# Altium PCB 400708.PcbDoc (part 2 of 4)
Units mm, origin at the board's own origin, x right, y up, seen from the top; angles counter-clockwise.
Board outline 117 x 63.5 mm, 4 copper layers (Top Layer, Mid-Layer 1, Mid-Layer 2, Bottom Layer), stack 1.556 mm thick; 226 components, 168 nets, 912 pads, 2002 vias.
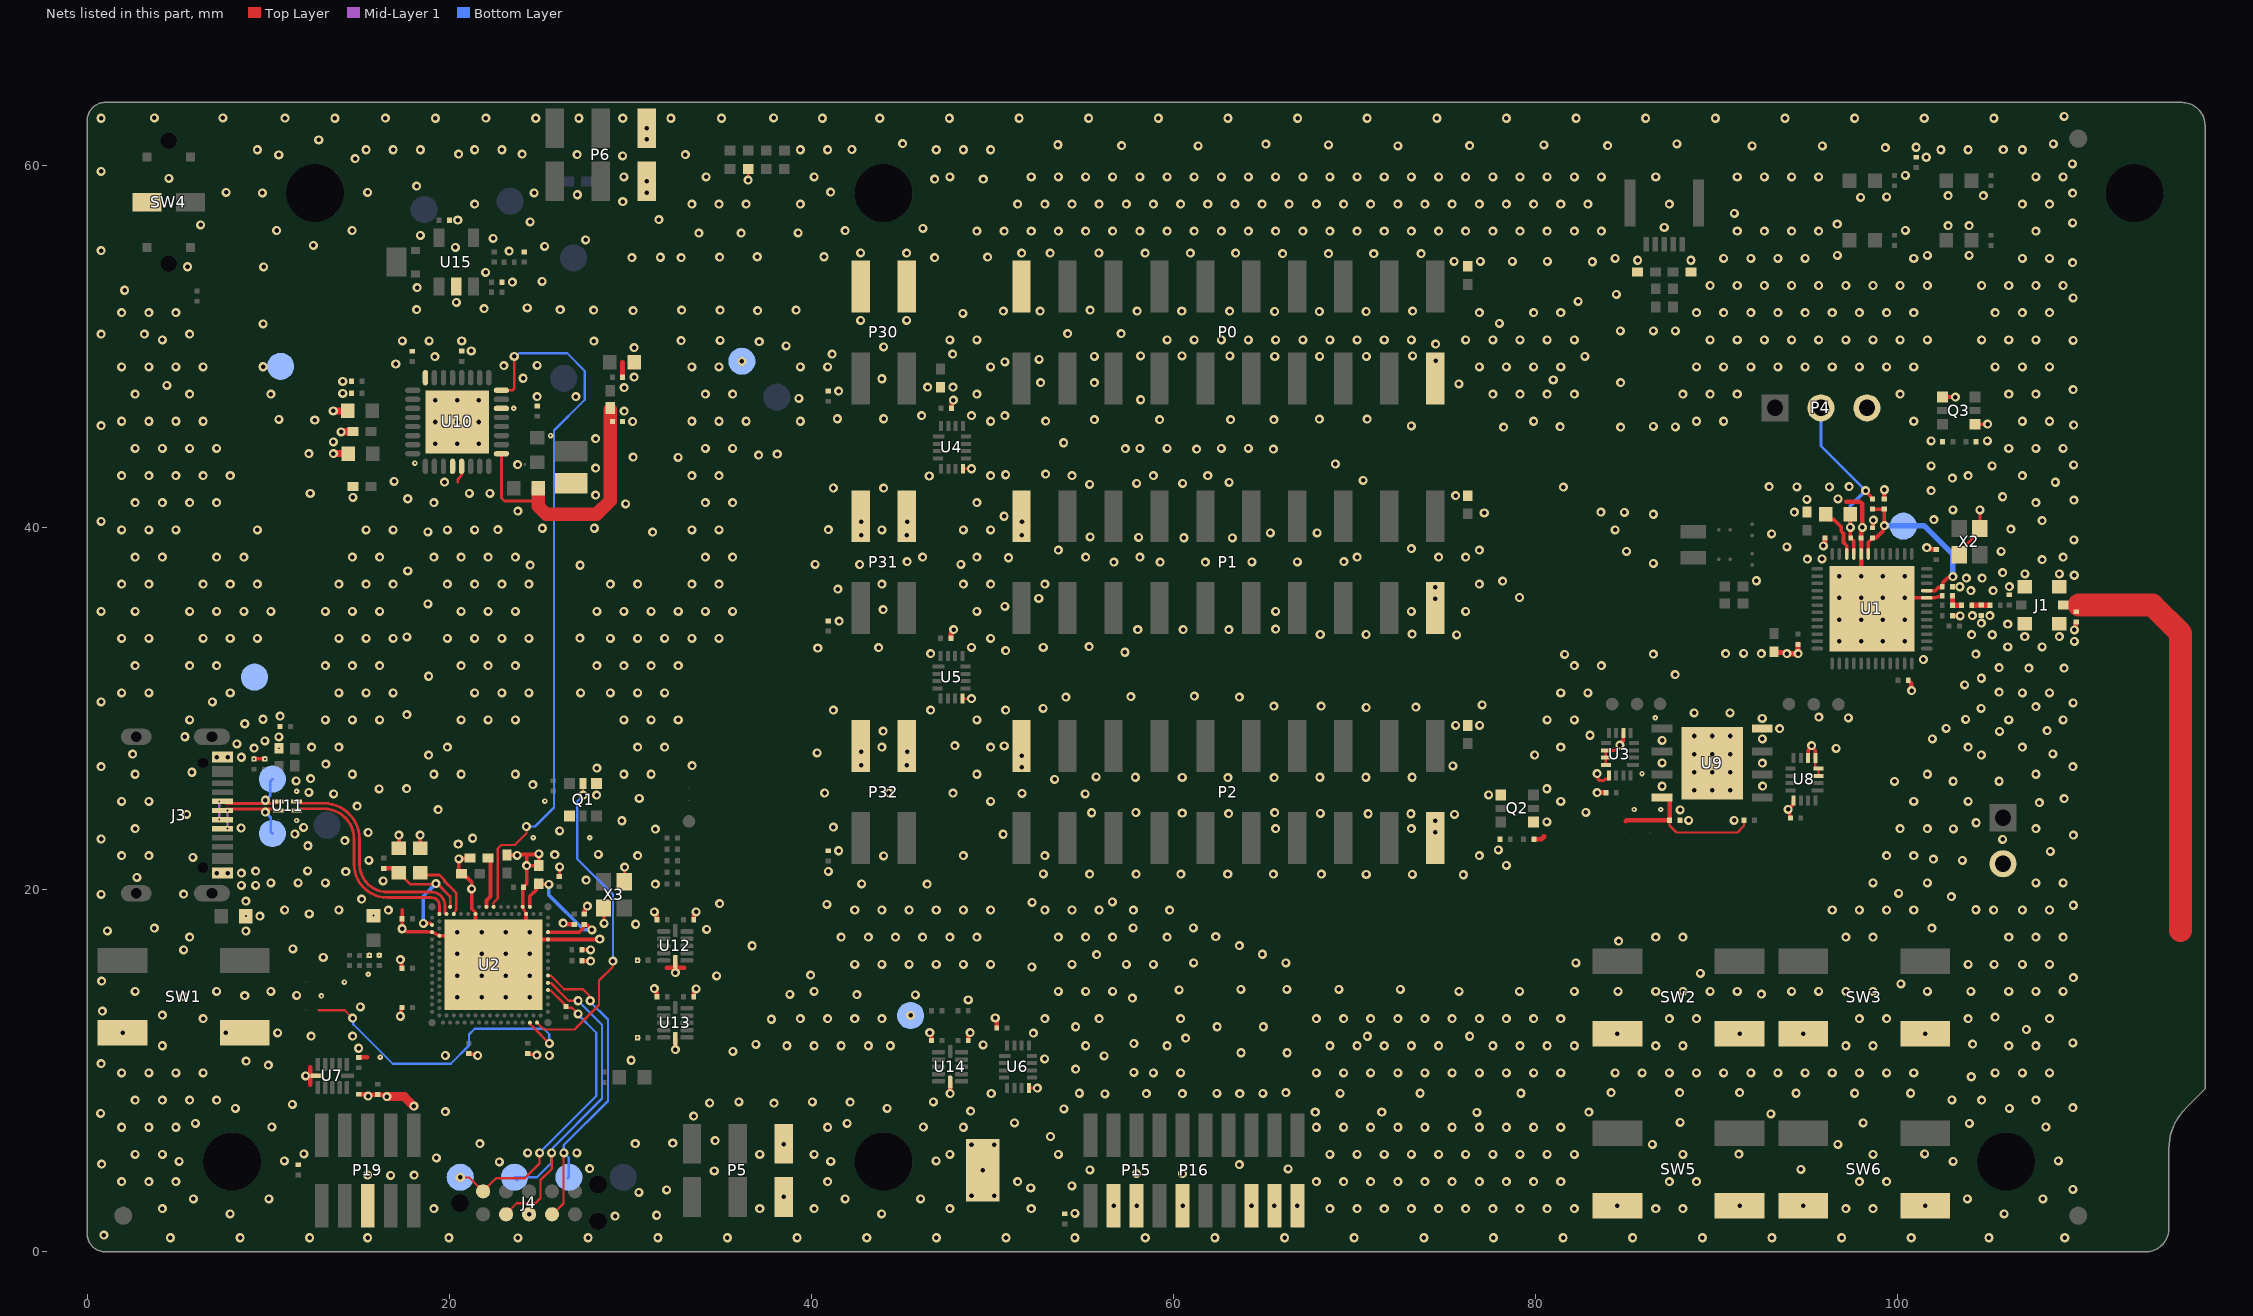
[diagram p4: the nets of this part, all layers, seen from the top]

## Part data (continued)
L3 L4: library part L0201-3n5-HQ-Murata, "Inductor, 500mA, ±0.1ｎH, 170mOhm", Manufacturer=Murata, Manufacturer Part Number=LQP03HQ3N5B02, Part number IPS=N.A., Part number NEMS=100300222, Supplier Part Number 1=490-13925-1-ND
L8: library part L0806-2µ2-2500mA-73mOhm-CIGT201610EH2R2MNE, "Inductor, Irms=2.5A, Isat=2.9A, ±20%, DCR=73mΩ", Manufacturer="Samsung Electro-Mechanics America", Manufacturer Part Number=CIGT201610EH2R2MNE, Part number IPS=N.A., Part number NEMS=100300400, Part number Norautron=26521789, Supplier Part Number 1=1276-6901-1-ND
LABEL1: library part Label_12x12, "PCA version label, stick-on, 12x12mm", Manufacturer="Ellco Etikett", Manufacturer Part Number=A33512‐01, Part number IPS=N.A., Part number NEMS=101200028
LD1 LD2 LD3 LD4 LD5: library part "VS 25C7M5", "LED, Green, 0603, 573nm, Vf=2.0V, 24mcd, - 40 to +85°C", Manufacturer="Victory Electronics", Part number IPS="00000001274, 00000009961", Part number NEMS=101400097, Part number Norautron=26313411, Supplier Part Number 1=N.A.
LOGO1: library part "Nordic Logo lying", "Nordic logo lying", Manufacturer=N.A., Part number NEMS=101100001
LOGO2: library part "WEEE Symbol 3x4.5mm", "WEEE Directive symbol", Manufacturer=N.A., Part number NEMS=101100006
LOGO3: "Segger logo, small size", Manufacturer=N.A., Part number NEMS=101100004
LOGO4: library part CE_logo, "CE (Conformité_Européenne) logo", Manufacturer=N.A., Part number NEMS=101100010
NT2: library part "2 pin starpoint", "Starpoint", Manufacturer=N.A., Part number NEMS=100500603
P0 P1 P2: library part "Pin Header 2x10 SMD, 2.54mm", "Pin Header 2x10, 2.54mm (100mil) SMD", Manufacturer=WCON, Manufacturer Part Number=1125-1210S0M116CR09, Part number IPS=N.A., Part number NEMS=100500738
P3: "Pin List 1x2, 2.54mm (100mil)", Manufacturer=N.A., Part number NEMS=100500297
P4: "Pin List 1x3, 2.54mm (100mil)", Manufacturer=N.A., Part number NEMS=100500304
P5 P6: library part "Pin List 1x3 SMD", "Pin List 1x3, 2.54mm (100mil), SMD", Manufacturer=WCON, Manufacturer Part Number=1125-1103S0M116CR04, Part number IPS=N.A., Part number NEMS=100500306, Part number Norautron=26470016
P15 P19: library part "Pin Header 2x5 SMD, 1.27mm, KS", "Pin Header 2x5, 1.27mm (50mil), SMD, Keying Shroud", Manufacturer=WCON, Manufacturer Part Number=3132-10MS0BK00R5, Part number IPS=N.A., Part number NEMS=100500261
P16: library part "Pin Header 2x10 SMD, 1.27mm, KS, N.C.", "Pin Header 2x10, 1.27mm (50mil), SMD, Keying Shroud", Manufacturer=WCON, Manufacturer Part Number=3132-20MS0BK00R1, Part number IPS=N.A., Part number NEMS=100500279
P30 P31 P32: "Pin Header 2x2, SMD, 2.54mm (100mil)", Manufacturer=WCON, Manufacturer Part Number=1125-1202S0M116CR03, Part number IPS=N.A., Part number NEMS=100500770
Q1 Q2 Q3: "MOSFET 2N-CH 60V 0.17A TSSOP6 (SOT363)", Manufacturer=Nexperia, Manufacturer Part Number=NX138AKSX, Part number IPS=N.A., Part number NEMS=101300207, Supplier Part Number 1=1727-2732-2-ND
Q4: library part PBSS4330PA,115, "30V, 3A, 2.1W, G=270, NPN Transistor", Manufacturer=Nexperia, Part number IPS=N.A., Part number NEMS=101300184, Supplier Part Number 1=1727-5112-1-ND‎
R1 R2 R19 R20: library part R0201-680, "Resistor, ±1%, 0.05W", Manufacturer=N.A., Part number NEMS=100100040
R3 R9 R38: library part R0201-0R, "Resistor, ±5%, 0.05W", Manufacturer=N.A., Part number IPS=00000003245, Part number NEMS=100100001
R4 R37 R41 R42: library part R0201-10k, "Resistor, ±1%, 0.05W", Manufacturer=N.A., Part number IPS=00000001255, Part number NEMS=100100065, Part number Norautron=26107101
R5: library part R0201-560, "Resistor, ±1%, 0.05W", Manufacturer=N.A., Part number NEMS=100100038
R6 R8 R13 R14 R15 R16 R17 R23 R31 R32 R35 R39 R56: library part R0201-100k, "Resistor, ±1%, 0.05W", Manufacturer=N.A., Part number IPS=00000001419, Part number NEMS=100100080, Part number Norautron=26108487
R7: library part R0201-47R, "Resistor, ±1%, 0.05W", Manufacturer=N.A., Part number IPS=00000004794, Part number NEMS=100100022, Part number Norautron=26108300
R10 R11 R12 R18 R27: library part R0201-1M0, "Resistor, ±1%, 0.05W", Manufacturer=N.A., Part number IPS=00000001418, Part number NEMS=100100093, Part number Norautron=26107108
R21 R22 R25 R28 R29 R30 R33 R34: library part R0402-0R, "Resistor, ±5%, 0.063W", Manufacturer=N.A., Part number IPS=00000007128, Part number NEMS=100100109, Supplier Part Number 1=146-9661
R24: library part R0402-TBD, "Chip Res 0402", Manufacturer=N.A., Part number NEMS=100100282
R26: library part R0201-47k, "Resistor, ±1%, 0.05W", Manufacturer=N.A., Part number IPS=00000001423, Part number NEMS=100100076
R36: library part R0201-1k0, "Resistor, ±1%, 0.05W", Manufacturer=N.A., Part number IPS=00000005786, Part number NEMS=100100043
R40: library part R0201-2R2, "Resistor, ±1%, 0.05W", Manufacturer=N.A., Part number NEMS=100100006, Part number Norautron=26470029
R43: library part R0201-33k, "Resistor, ±1%, 0.05W", Manufacturer=N.A., Part number IPS=00000001708, Part number NEMS=100100073
S1: "Giteki symbol", Manufacturer=N.A., Part number NEMS=101100011
SB1 SB8 SB10: Manufacturer=N.A., Part number NEMS=100500458
SB2 SB9 SB11: library part "Solderbridge Shorted", "Shorted Solderbridge", Manufacturer=N.A., Part number NEMS=100500459
SB3 SB4: library part "Solderbridge Shorted 0.4mm", "Shorted Solderbridge", Manufacturer=N.A., Part number NEMS=100500561
SB5 SB6: library part "Solderbridge 0.4mm", Manufacturer=N.A., Part number NEMS=100500560
SW1 SW2 SW3 SW5 SW6: library part Switch-PB-6.2x6.3mm-SMD, "Tactile Switch, SPNO, SMD, 160gf, 6.2x6.3x2.5mm", Manufacturer=Dailywell, Manufacturer Part Number=TS604VM1-025BR-R, Part number IPS=00000007812, Part number NEMS="101500001, 101500133", Part number Norautron=N.A.
SW4: library part Switch-Slide-RA-J-Lead-DPDT-8.5x3.5mm_C&K, "SMD slide Switch (ON-ON)", Manufacturer=C&K, Manufacturer Part Number=JS202011JAQN, Part number IPS=00000007811, Part number NEMS=101500037, Part number Norautron=N.A., Supplier Part Number 1=CKN10722CT-ND
TP1 TP2 TP3 TP4 TP5 TP6 TP8 TP9 TP10 TP11 TP12 TP13 TP14 TP15 TP16 TP17 TP18: library part TP_SMD_Ø1.5MM, "1.5mm circular SMD testpad", Manufacturer="Nordic Semiconductor", Manufacturer Part Number=N.A., Part number NEMS=100500477
TP7 TP19 TP20 TP21 TP23 TP24 TP25: library part TP_SMD_Ø0.7MM, "0.7mm circular SMD testpad", Manufacturer="Nordic Semiconductor", Manufacturer Part Number=N.A., Part number NEMS=100500474
TP22: library part "TP - S1751-46R", "PC TEST POINT TIN SMD L", Manufacturer=Harwin, Manufacturer Part Number=S1751-46R, Part number IPS=N.A., Part number NEMS=100500525, Supplier Part Number 1=952-1478-1-ND
U1: library part nRF54L15-QFAAC00, "Multi-protocol Bluetooth Low Energy, IEEE 802.15.4 and 2.4GHz proprietary Wireless MCU", Manufacturer="Nordic Semiconductor", Part number IPS=N.A., Part number NEMS=102000382
U2: library part nRF5340-QKAAD0, "Multi-protocol Bluetooth Low Energy, IEEE 802.15.4, ANT and 2.4GHz proprietary system-on-chip", Manufacturer="Nordic Semiconductor", Part number IPS=N.A., Part number NEMS=102000216, Part number Norautron=NOD26470035
U3 U8: "Low-Capacitance, 2:1 (SPDT) 4-Channel, analog switch", Manufacturer="Texas Instruments", Manufacturer Part Number=TMUX1574RSVR, Part number IPS=N.A., Part number NEMS=101900850, Supplier Part Number 1=296-53445-2-ND
U4 U5 U6: "Low-Capacitance, 1:1 (SPST) 4-Channel, analog switch", Manufacturer="Texas Instruments", Manufacturer Part Number=TMUX1511RSVR, Part number IPS=N.A., Part number NEMS=101900847, Supplier Part Number 1=296-53443-2-ND
U7 U12 U13 U14: library part TXB0104RUTR, "4-Bit Bidirectional Level-Shifter/Voltage Translator with Automatic Direction Sensing", Manufacturer="Texas Instruments", Part number IPS=N.A., Part number NEMS=101900856, Supplier Part Number 1=296-25888-2-ND
U9: library part MX25R6435FZNIL0, "Ultra low power, 64M-bit, serial multi I/O flash memory", Manufacturer=Macronix, Part number IPS=00000004370, Part number NEMS=101900438, Part number Norautron=N.A.
U10: "Li-Ion/Li-Polymer USB-C battery charger with high efficiency buck regulators, LDOs or load switches, LED drivers, TWI and VBUSOUT", Manufacturer="Nordic Semiconductor", Part number IPS=N.A., Part number NEMS=102000306
U11: "2 Line Common mode filter with ESD protection for USB 2.0 interface", Manufacturer=STMicroelectronics, Part number IPS=N.A., Part number NEMS=100800034, Supplier Part Number 1=497-13420-2-ND
U15: library part TLV271CW5-7, "Dual rail to rail CMOS Amplifier", Manufacturer="Diodes Incorporated", Part number IPS=N.A., Part number NEMS=101900398, Supplier Part Number 1=TLV271CW5-7DICT-ND
X1: library part XTAL_SMD2012_32.768kHz_9pF_TXC, "XTAL SMD 2012, 32.768kHz, 9pF, ±20ppm", Manufacturer="TXC Corporation", Manufacturer Part Number=9HT11-32.768KDZC-T, Part number IPS=N.A., Part number NEMS=101600107, Supplier Part Number 1=887-1426-2-ND
X2 X3: library part XTAL_SMD2016_32MHz_8pF_Golledge, "XTAL SMD 2016, 32MHz, Cl=8pF, Tol: ±10ppm, Stab: ±15ppm", Manufacturer=Golledge, Manufacturer Part Number=MP06003, Part number IPS=00000001431, Part number NEMS=101600041, Part number Norautron=N.A.

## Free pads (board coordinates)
  round 3.2 hole 3.2 unplated: 1(8.004,5) 1(12.604,58.5) 1(44.004,5) 1(44.004,58.5) 1(106.004,5) 1(113.104,58.5)

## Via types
v1: diameter 0.5, hole 0.25, Top Layer to Bottom Layer, tented both sides, 1905 vias
v2: diameter 0.3, hole 0.1, Top Layer to Mid-Layer 1, tented top, 77 vias
v3: diameter 0.3, hole 0.1, Top Layer to Mid-Layer 1, tented both sides, 20 vias

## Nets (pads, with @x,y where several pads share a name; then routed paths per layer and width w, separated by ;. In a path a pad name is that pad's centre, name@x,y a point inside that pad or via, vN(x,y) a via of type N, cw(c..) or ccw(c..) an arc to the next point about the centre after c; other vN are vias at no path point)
ANT: C38.2 J1.3 | length 22.7
  Top Layer w1.27: 110.033,35.73 114.1,35.73 115.66,34.171 115.66,17.748
DBGR'_N: J3.A7 J3.B7 TP17.1 U11.2 | length 5.5
  Top Layer w0.153: J3.B7@7.489,24.875 ccw(c7.727,25.113) 7.727,24.776 10.322,24.776 ccw(c10.322,25.141) U11.2@10.579,24.883
  Mid-Layer 1 w0.127: v2(7.3,23.884) v2(7.3,24.884)
  Bottom Layer w0.153: v1(9.85,24.95) 10.125,25.225 10.125,26 TP17.1@10.24,26.115
DBGR'_P: J3.A6 J3.B6 TP18.1 U11.3 | length 5.5
  Top Layer w0.153: J3.A6@7.489,24.375 cw(c7.727,24.137) 7.727,24.473 10.361,24.473 cw(c10.361,24.165) U11.3@10.579,24.383
  Mid-Layer 1 w0.127: v2(7.763,23.385) v2@7.763,24.374
  Bottom Layer w0.153: v1(9.85,24.3) 10.147,24.003 10.147,23.206 TP18.1@10.24,23.113
  other v2: 7.763,24.385
DBGR_BUTTON: SB2.2 U2.AL27 | length 17.6
  Top Layer w0.125: SB2.2@12.8,13.364 12.815,13.35 14.237,13.35 v1(14.675,12.912) ; U2.AL27@24.46,12.664 24.46,12.637 24.51,12.587 24.51,12.555 24.631,12.434 24.631,12.427 v1(25.54,11.518)
  Top Layer w0.15: U2.AL27@24.46,12.622 U2.AL27@24.46,12.637
  Bottom Layer w0.125: v1(14.675,12.912) 14.703,12.884 14.703,12.572 16.888,10.387 20.087,10.387 21.1,11.4 21.1,12.009 21.416,12.325 25.244,12.325 25.54,12.03 v1(25.54,11.518)
DBGR_LED: Q1.2 U2.AL29 | length 17.5
  Top Layer w0.125: U2.AL29@24.86,12.664 25.237,12.288 26.938,12.288 27.124,12.474 28.286,13.636 28.286,14.986 29.023,15.723 29.023,16.037 v1(29.05,16.064) ; v1(27.401,25.234) Q1.2@27.401,25.71
  Bottom Layer w0.125: v1(27.401,25.234) 27.401,25.199 27.079,24.878 27.079,21.71 29.05,19.739 v1(29.05,16.064)
DBGR_N: U2.B4 U11.7 | length 12.6
  Top Layer w0.153: U11.7@11.579,24.883 ccw(c11.833,25.137) 11.833,24.778 13.084,24.778 cw(c13.084,22.81) 15.053,22.81 15.053,21.422 ccw(c16.6,21.422) 16.6,19.875 19.033,19.875 cw(c19.033,19.138) 19.77,19.138 19.77,18.755 ccw(c19.86,18.755) U2.B4@19.86,18.664
DBGR_P: U2.B2 U11.6 | length 12
  Top Layer w0.153: U11.6@11.579,24.383 cw(c11.801,24.161) 11.801,24.475 13.084,24.475 cw(c13.084,22.81) 14.75,22.81 14.75,21.422 ccw(c16.6,21.422) 16.6,19.572 19.033,19.572 cw(c19.033,19.138) 19.467,19.138 19.467,18.664 U2.B2@19.46,18.664
DBGR_RESET: J4.10 R6.1 TP4.1 U2.AC31 | length 17.6
  Top Layer w0.125: v1(20.616,4.115) 21.107,4.115 J4.10@21.878,3.344 22.609,4.075 24.2,4.075 25.001,4.876 v1(25.001,5.475) ; U2.AC31@25.46,14.464 25.479,14.445 25.616,14.445 26.372,13.689 26.372,13.628 26.517,13.483 26.792,13.483 v1(27.125,13.15)
  Bottom Layer w0.125: v1(25.001,5.475) 28.132,8.606 28.132,12.107 27.125,13.114 v1(27.125,13.15)
DBGR_SWDCLK: J4.4 TP6.1 U2.W31 | length 18
  Top Layer w0.125: U2.W31@25.46,15.264 25.471,15.254 25.624,15.254 26.363,14.515 27.124,14.515 27.393,14.515 27.732,14.176 27.732,13.943 v1(27.8,13.875) ; J4.4@25.688,2.074 25.724,2.074 26.324,2.674 26.324,5.459 v1(26.34,5.475)
  Bottom Layer w0.125: TP6.1@26.558,4.067 TP6.1@26.564,4.062 ; TP6.1@26.616,4.125 26.616,5.198 v1(26.34,5.475) 26.34,5.903 28.775,8.339 28.775,12.832 27.8,13.808 v1(27.8,13.875)
DBGR_SWDIO: J4.2 TP5.1 U2.AA31 | length 20.4
  Top Layer w0.125: J4.2@23.148,2.074 23.148,2.099 23.74,2.69 24.771,2.69 25.053,2.972 25.053,3.968 25.667,4.582 v1(25.667,5.475) ; U2.AA31@25.46,14.864 25.471,14.854 25.624,14.854 26.603,13.875 v1(27.125,13.875)
  Bottom Layer w0.125: TP5.1@23.616,4.125 24.851,4.125 25.667,4.94 v1(25.667,5.475) 25.738,5.547 25.738,5.76 28.452,8.473 28.452,12.548 v1(27.125,13.875)
  Bottom Layer w0.15: TP5.1@23.616,4.115 TP5.1@23.759,3.972
DCC: L1.2 U1.46 | length 2.8
  Top Layer w0.2: L1.2@96.053,40.758 96.053,40.733 96.328,40.458 96.496,40.458 96.906,40.048 96.906,39.818 97.033,39.691 97.033,39.186 97.205,39.014 U1.46@97.205,38.555
DECD: C1.2 FB1.1 L1.1 P4.2 U1.45 | length 10.9
  Top Layer w0.2: L1.1@97.414,40.798 v1(97.414,40.022) 97.414,39.46 C1.2@97.435,39.439 97.435,39.424 97.47,39.389 97.485,39.389 97.605,39.269 97.605,38.78 U1.45@97.605,38.555 ; v1(98.25,42.05) 98.25,42.024 98.583,41.691 98.583,41.637 FB1.1@98.637,41.637
  Bottom Layer w0.15: P4.2@95.785,46.625 95.785,44.515 v1(98.25,42.05)
  Bottom Layer w0.2: v1(97.414,40.022) 97.414,41.214 v1(98.25,42.05)
DECRF: C2.2 C5.2 C12.1 FB1.2 TP2.1 U1.33 U1.43 | length 11.2
  Top Layer w0.2: U1.43@98.405,38.555 98.405,39.204 98.668,39.467 98.856,39.467 99.236,39.847 99.236,40.066 v1(99.294,40.123) C2.2@99.294,41.032 FB1.2@98.633,41.032 ; U1.33@101.63,36.53 102.093,36.53 102.263,36.7 102.453,36.7 102.488,36.735 102.488,36.745 102.523,36.78 102.523,36.975 102.795,37.246 103.021,37.246 v1(103.078,37.304)
  Bottom Layer w0.15: TP2.1@100.252,40.123 TP2.1@100.273,40.144
  Bottom Layer w0.3: v1(99.294,40.123) 100.252,40.123 101.478,40.123 103.078,38.523 v1(103.078,37.304)
GND: C1.1 C2.1 C3.1 C4.2 C5.1 C6.1 C7.2 C8.2 C9.1 C10.2 C11.2 C12.2 C13.2 C14.2 C15.2 C16.1 C17.2 C18.2 C19.1 C20.2 C21.2 C22.2 C23.1 C25.1 C26.1 C28.1 C29.2 C30.2 C31.2 C32.1 C33.2 C34.2 C35.2 C36.2 C37.2 C38.1 C39.1 C40.2 C41.1 C42.2 C43.2 C44.2 C45.1 C46.1 C47.1 C48.1 C49.2 C50.1 C51.1 C52.1 C53.1 C54.2 C55.1 C56.1 C57.1 C58.2 C59.2 C60.2 C61.1 C62.1 C63.1 C64.1 C65.2 C66.2 C67.2 C68.1 C69.2 C70.1 C72.2 C73.1 C74.2 C75.2 C76.2 C77.2 C78.2 C79.2 J1.2 J3.A1 J3.A12 J4.3 NT2.1 P0.2 P0.19 P1.2 P1.19 P2.2 P2.19 P3.2 P4.3 P5.1 P6.1 P15.3 P15.5 P15.9 P16.3 P16.5 P16.9 P16.15 P16.17 P16.19 P19.5 P30.2 P30.4 P31.2 P31.4 P32.2 P32.4 Q1.1 Q1.4 Q2.1 Q2.4 Q3.1 Q3.4 R4.1 R7.2 R10.2 R11.2 R12.2 R18.1 R26.2 R27.2 R30.2 R32.2 R37.1 R42.1 R56.2 SW1.1 SW2.1 SW3.1 SW4.2 SW5.1 SW6.1 TP12.1 TP13.1 TP14.1 TP15.1 TP22.1 U1.32 U1.44 U1.49 U2.104 U2.A25 U2.B12 U2.B26 U2.G1 U2.H2 U2.J31 U3.6 U3.10 U3.11 U3.12 U3.13 U4.8 U5.8 U6.8 U7.6 U8.3 U8.4 U8.5 U8.6 U8.13 U9.4 U9.9 U10.6 U10.16 U10.28 U10.29 U10.33 U11.5 U11.8 U12.6 U13.6 U14.6 U15.2 X2.2 X2.4 X3.2 X3.4 | length 75.6
  Top Layer w0.125: C65.2@83.9,25.385 C65.2@83.905,25.39 ; U3.10@83.9,27.7 U3.11@83.9,27.3 U3.12@83.9,26.9 84.028,26.9 U3.12@84.075,26.853 ; U8.5@95.475,27.275 95.475,26.747 95.522,26.7 U8.4@95.65,26.7 U8.3@95.65,26.3
  Top Layer w0.15: U10.16@18.678,48.31 U10.16@18.692,48.296 ; 20.478,42.525 20.478,42.678 20.691,42.891 U10.29@20.692,43.396 ; C37.2@26.096,20.744 26.103,20.751 26.103,21.258 v1(26.11,21.265) ; X3.4@28.534,18.99 28.56,18.965 v1(28.56,18.147) ; X3.2@29.677,20.448 29.7,20.471 v1(29.7,21.258) ; v1(36.525,59.207) R30.2@36.525,59.83 ; U5.8@48.36,30.561 v1(48.86,30.561) ; U4.8@48.378,43.262 v1(48.86,43.262) ; U6.8@52.025,9.05 v1(52.496,9.05) ; v1(83.425,26.425) 83.472,26.378 83.472,26.1 83.53,26.042 83.792,26.042 83.875,26.125 84.04,26.125 84.075,26.16 U3.13@84.075,26.325 ; U3.10@83.9,27.7 84.375,27.7 v1(84.675,28) ; X2.4@103.418,38.509 103.768,38.859 103.768,39.026 104.218,39.476 104.218,39.609 X2.2@104.568,39.959 ; X2.2@104.568,39.934 X2.2@104.568,39.959 ; v1(104.568,40.987) X2.2@104.568,39.959
  Top Layer w0.165: U2.A25@24.06,19.064 U2.B26@24.26,18.664
  Top Layer w0.187: U2.G1@19.06,17.664 U2.H2@19.46,17.464 U2.104@20.16,17.464 ; v1(21.245,20.052) 21.245,18.96 21.453,18.752 21.453,18.672 U2.B12@21.46,18.664
  Top Layer w0.188: 18.183,17.694 18.832,17.694 18.856,17.669 19.055,17.669 U2.G1@19.06,17.664
  Top Layer w0.2: v3(9.225,27.235) v3(9.825,27.235) ; C42.2@17.231,22.302 v1(17.231,23.024) ; v1(17.308,13.017) 17.365,13.074 17.365,13.436 C20.2@17.428,13.499 ; v1(17.313,16.149) 17.369,16.094 17.369,15.659 C18.2@17.404,15.624 ; 17.404,18.9 17.404,18.864 C13.2@17.404,18.401 v1(17.404,17.853) 17.485,17.853 17.644,17.694 18.183,17.694 ; C43.2@18.4,22.302 v1(18.4,23.025) ; v1@20.529,21.735 20.529,21.041 20.679,20.891 C45.1@20.694,20.891 ; v1(20.538,21.706) 20.562,21.73 21.236,21.73 C39.1@21.262,21.756 ; C45.1@20.719,20.916 20.894,20.741 20.932,20.741 21.243,20.429 21.243,20.054 v1(21.245,20.052) ; C22.2@21.092,10.954 21.127,10.919 21.431,10.919 21.5,10.85 v1(21.581,10.85) ; U2.A25@24.06,19.064 24.06,19.987 24.085,20.012 24.085,20.134 24.285,20.334 v1(24.285,21.34) ; 24.262,21.951 24.285,21.929 v1(24.285,21.34) ; C34.2@24.343,10.954 24.378,10.919 24.806,10.919 v1(24.85,10.875) ; v1(24.96,21.988) 24.957,21.984 24.957,21.343 C32.1@24.953,21.34 v1(24.285,21.34) ; Q1.1@27.964,25.91 28.158,25.716 Q1.1@28.164,25.716 ; v1(84.675,28) 84.675,28.05 84.875,28.25 U3.6@84.875,28.675 ; C66.2@94.1,23.971 94.065,24.006 94.065,24.273 93.978,24.359 v1(93.978,24.44) 94.265,24.727 94.265,24.915 U8.13@94.275,24.925 ; U8.6@95.075,27.275 95.075,27.715 v1@95.275,27.915 ; v1(95.275,27.965) v1@95.275,27.915 ; U8.5@95.475,27.275 95.475,27.715 v1@95.275,27.915 ; C12.2@98.633,40.002 98.659,40.027 98.659,40.403 v1(98.684,40.428) ; U1.49@100.443,36.13 U1.32@101.63,36.13 102.06,36.13 C6.1@102.487,36.244 ; Q3.1@102.5,47.225 v1(103.216,47.225) ; Q3.4@104.3,45.725 v1@105.016,45.725
  Top Layer w0.203: R7.2@27.345,16.687 v1(27.823,16.687) ; C35.2@27.353,16.078 27.36,16.071 27.816,16.071 v1(27.823,16.064)
  Top Layer w0.225: U2.104@21.46,17.264 U2.B12@21.46,18.664 ; C31.2@23.15,21.905 C31.2@23.16,21.915 ; C31.2@23.211,21.915 23.751,21.915 v1(23.759,21.907) 23.804,21.951 24.262,21.951 24.924,21.951 v1(24.96,21.988) ; U2.B26@24.26,18.664 24.26,17.264 28.314,17.264 v1(28.325,17.275) ; C33.2@27.459,18.661 27.474,18.661 27.496,18.683 27.496,18.879 27.644,19.027 v1(27.644,19.101)
  Top Layer w0.25: v1(12.075,9.725) U7.6@12.7,9.725 ; 12.34,9.244 12.34,10.2 ; C14.2@15.004,8.707 15.014,8.697 15.36,8.697 15.457,8.6 v1(15.525,8.6) 15.593,8.6 15.675,8.682 16.054,8.682 R18.1@16.064,8.692 16.074,8.682 16.391,8.682 16.493,8.58 v1(16.56,8.58) ; C53.1@15.004,10.744 15.468,10.744 ; v1(26.299,18.167) 26.367,18.167 26.433,18.101 26.899,18.101 C36.2@26.909,18.091 ; v1(31.346,14.539) 31.346,14.471 31.471,14.346 31.471,14.114 C76.2@31.481,14.104 ; v1(31.346,18.789) 31.346,18.721 31.471,18.596 31.471,18.364 C74.2@31.481,18.354 ; 32.025,15.69 32.981,15.69 ; v1(32.5,11.175) U13.6@32.5,11.8 ; v1(32.5,15.425) U12.6@32.5,16.05 ; C77.2@33.518,14.094 33.528,14.104 33.528,14.341 33.653,14.466 v1(33.653,14.533) ; C75.2@33.518,18.354 33.528,18.364 33.528,18.596 33.653,18.721 v1(33.653,18.789) ; v1(46.555,12.114) 46.555,12.046 46.644,11.957 46.644,11.689 C78.2@46.654,11.679 ; v1(47.675,8.75) U14.6@47.675,9.375 ; C15.2@47.718,33.903 47.728,33.913 47.728,34.168 47.868,34.307 v1(47.868,34.375) ; C10.2@47.752,46.607 47.762,46.617 47.762,46.894 47.856,46.989 v1(47.856,47.056) ; C79.2@48.68,11.679 48.69,11.689 48.69,11.956 48.78,12.046 v1(48.78,12.114) ; v1(50.172,12.931) 50.172,12.864 50.245,12.79 50.245,12.379 C49.2@50.255,12.369 ; v1@95.915,39.068 v1@95.915,39.073 ; 97.195,41.453 97.938,41.453 98.074,41.317 v1(98.074,40.022) 98.074,39.954 98.015,39.895 98.015,39.449 C1.1@98.005,39.439 U1.44@98.005,38.555 v1(98.005,37.33) ; C2.1@99.294,41.602 v1(99.294,42.104) ; C8.2@100.61,31.575 100.61,31.56 100.62,31.55 100.624,31.55 100.77,31.404 100.77,31.027 v1(100.792,31.005) ; v1(101.63,38.904) 101.698,38.904 101.784,38.818 102.154,38.818 C4.2@102.164,38.808 ; C60.2@103.058,35.149 103.063,35.144 103.466,35.144 v1(103.471,35.139) ; v1(109.789,34.36) 109.789,34.427 109.855,34.493 109.855,34.785 109.865,34.795 C38.1@109.88,34.795
  Top Layer w0.254: X3.4@28.531,18.994 X3.4@28.534,18.99 ; X3.2@29.677,20.448 X3.2@29.681,20.444
  Top Layer w0.27: C25.1@29.59,48.321 29.59,49.147 ; R10.2@79.925,22.798 80.344,22.798 80.488,22.942 ; v1(83.425,25.375) 83.429,25.371 83.908,25.371 C65.2@83.908,25.365 ; C19.1@85.652,54.123 C19.1@85.654,54.124 ; v1@85.654,54.779 v1(85.656,54.781) ; v1(95.915,39.006) 95.915,39.068 96,39.153 C11.2@96,39.439
  Top Layer w0.3: C41.1@93.186,33.155 93.23,33.112 93.798,33.112 93.855,33.055 v1(93.909,33.055) v1(94.53,33.055) 94.518,33.067 C7.2@94.518,33.564 ; C5.1@103.084,36.75 103.454,36.75 v1(103.459,36.745)
  Top Layer w0.4: v1(13.6,46.456) 14.401,46.456 C26.1@14.404,46.459 ; v1@13.61,44.1 C54.2@14.425,44.1 ; v1(14.032,45.304) 14.037,45.308 14.679,45.308 C23.1@14.684,45.313 ; v1(90.775,28.5) U9.9@90.975,28.5 ; U9.4@92.545,28.905 U9.4@92.547,28.903 ; v1@92.547,28.344 v1(92.549,28.341)
  Top Layer w0.5: v1(16.56,8.58) 17.53,8.58 v1(18.055,8.055)
  other v1: 4.604,0.78 8.451,0.78 12.298,0.78 15.498,0.78 19.991,0.78 23.8,0.775 27.685,0.78 31.532,0.78 35.379,0.78 39.225,0.78 43.072,0.78 46.919,0.78 50.766,0.78 54.575,0.78 58.459,0.78 62.306,0.78 66.153,0.78 70,0.78 73.847,0.78 77.693,0.78 81.54,0.78 85.387,0.78 89.234,0.78 93.081,0.78 96.927,0.78 100.774,0.78 105.063,0.78 109.254,0.78 0.929,0.925 29.175,1.975 31.471,2.025 24.418,2.074 7.9,2.1 43.9,2.1 105.9,2.1 54.575,2.125 4.162,2.387 19.162,2.387 37.162,2.387 40.162,2.387 47.662,2.387 52.162,2.387 68.662,2.387 70.162,2.387 71.662,2.387 73.162,2.387 74.662,2.387 76.162,2.387 77.662,2.387 79.162,2.387 80.662,2.387 82.162,2.387 86.662,2.387 88.162,2.387 97.162,2.387 98.662,2.387 56.708,2.553 57.978,2.553 60.518,2.553 64.328,2.55 65.598,2.55 66.868,2.55 84.543,2.561 91.293,2.561 94.804,2.561 101.554,2.561 5.875,2.925 10.046,2.925 41.875,2.925 46.046,2.925 103.875,2.925 108.046,2.925 38.5,3.04 48.86,3.097 50.124,3.097 30.488,3.282 32.023,3.426 109.704,3.458 52.134,3.531 54.4,3.65 1.912,3.887 3.412,3.887 4.912,3.887 40.912,3.887 51.412,3.887 67.912,3.887 69.412,3.887 70.912,3.887 72.412,3.887 73.912,3.887 75.412,3.887 76.912,3.887 78.412,3.887 79.912,3.887 81.412,3.887 87.412,3.887 88.912,3.887 97.912,3.887 99.412,3.887 16.766,4.224 15.498,4.244 18.07,4.246 57.978,4.32 60.525,4.32 34.65,4.473 49.475,4.5 55.403,4.531 94.677,4.558 27.763,4.596 66.356,4.589 0.804,4.85 63.655,4.826 22.784,4.973 5.084,5 41.084,5 103.084,5 10.905,5.025 46.905,5.025 108.905,5.025 19.296,5.197 2.662,5.387 4.162,5.387 37.162,5.387 40.162,5.387 47.662,5.387 53.662,5.387 68.662,5.387 70.162,5.387 71.662,5.387 73.162,5.387 74.662,5.387 76.162,5.387 77.662,5.387 79.162,5.387 80.662,5.387 82.162,5.387 88.162,5.387 91.25,5.4 98.662,5.387 11.982,5.412 101.518,5.411 24.343,5.475 27.058,5.475 48.86,5.922 50.125,5.922 86.474,5.941 96.721,5.941 38.5,5.945 21.707,5.978 30.285,5.979 32.356,6.013 34.7,6.15 53.225,6.375 1.912,6.887 3.412,6.887 4.912,6.887 10.208,6.9 40.912,6.887 46.208,6.9 48.412,6.887 67.912,6.887 69.412,6.887 70.912,6.887 72.412,6.887 73.912,6.887 75.412,6.887 76.912,6.887 78.412,6.887 79.912,6.887 81.412,6.887 108.208,6.9 5.99,7.1 41.99,7.1 103.99,7.1 51.236,7.125 98.114,7.125 88.004,7.15 33.514,7.5 93.025,7.627 0.75,7.65 67.85,7.72 76.775,7.706 71.525,7.722 82.963,7.722 19.793,7.752 48.81,7.772 53.969,7.9 8.2,7.925 44.2,7.925 106.2,7.925 109.704,7.975 11.343,8.151 34.393,8.225 37.95,8.213 42.149,8.275 36.015,8.282 40.066,8.282 46.754,8.282 2.662,8.387 4.162,8.387 5.662,8.387 7.162,8.387 103.025,8.4 104.662,8.387 107.662,8.387 56.225,8.725 49.951,8.75 58.517,8.747 60.515,8.747 62.419,8.756 63.68,8.747 64.959,8.76 69.225,8.756 54.822,8.763 73.64,8.763 79.213,8.763 94.409,8.763 97.65,8.763 100.735,8.763 66.229,8.798 84.193,8.798 87.974,8.798 91.293,8.798 104.09,9.675 1.912,9.887 3.412,9.887 4.912,9.887 6.412,9.887 58.912,9.887 60.412,9.887 67.912,9.887 69.412,9.887 70.912,9.887 72.412,9.887 73.912,9.887 75.412,9.887 76.912,9.887 78.412,9.887 79.912,9.887 81.412,9.887 84.412,9.887 85.912,9.887 87.412,9.887 88.912,9.887 90.412,9.887 91.912,9.887 93.412,9.887 94.912,9.887 96.412,9.887 97.912,9.887 99.412,9.887 100.912,9.887 105.412,9.887 106.912,9.887 108.412,9.887 57.825,9.915 54.61,10.1 10.015,10.313 0.78,10.4 8.794,10.535 30.058,10.588 52.9,10.666 56.185,10.825 19.8,10.85 25.54,10.85 63.748,11.002 66.297,11.002 35.675,11.075 15.004,11.25 4.162,11.387 38.662,11.387 40.162,11.387 41.662,11.387 43.162,11.387 44.375,11.389 55.162,11.387 59.662,11.387 68.662,11.387 70.162,11.387 71.662,11.387 73.162,11.387 74.662,11.387 77.662,11.387 79.162,11.387 80.662,11.387 82.162,11.387 86.662,11.387 88.162,11.387 97.162,11.387 98.662,11.387 106.162,11.387 107.662,11.387 49.504,11.435 36.95,11.458 104.16,11.475 57.825,11.513 109.704,11.55 60.688,11.814 12.375,11.925 14.675,11.925 70.725,11.913 76.377,11.913 84.543,12.058 91.293,12.058 94.804,12.061 101.554,12.061 52.282,12.088 1.963,12.097 7.65,12.097 10.529,12.102 107.135,12.286 54.61,12.438 62.432,12.438 64.982,12.438 37.8,12.851 6.412,12.887 39.412,12.887 40.912,12.887 42.412,12.887 43.912,12.887 52.912,12.887 55.912,12.887 60.412,12.887 67.912,12.887 69.412,12.887 70.912,12.887 72.412,12.887 73.912,12.887 75.412,12.887 76.912,12.887 78.412,12.887 79.912,12.887 81.412,12.887 87.412,12.887 88.912,12.887 97.912,12.887 99.412,12.887 103.912,12.887 108.412,12.887 105.406,12.975 4.162,13.078 45.5,13.064 0.852,13.3 15.1,13.535 48.68,13.928 57.748,14.025 20.46,14.064 21.794,14.064 23.127,14.064 24.46,14.064 5.335,14.1 8.713,14.152 11.579,14.167 38.825,14.221 42.533,14.208 45.762,14.2 92.496,14.239 2.662,14.387 7.162,14.387 10.162,14.387 40.162,14.387 53.662,14.387 55.162,14.387 56.662,14.387 75.791,14.393 79.134,14.393 82.162,14.387 84.575,14.393 86.662,14.387 88.162,14.387 89.662,14.387 91.162,14.387 94.162,14.387 95.662,14.387 97.162,14.387 98.662,14.387 101.662,14.387 104.068,14.393 106.162,14.387 107.662,14.387 109.162,14.387 60.325,14.475 63.741,14.5 66.288,14.5 69.15,14.5 72.55,14.5 100.205,14.806 0.804,14.954 109.729,15.15 20.46,15.264 21.794,15.264 23.127,15.264 24.46,15.264 34.775,15.247 39.977,15.285 89.122,15.387 52.199,15.738 42.412,15.887 43.912,15.887 45.412,15.887 46.912,15.887 48.412,15.887 49.912,15.887 54.412,15.887 57.412,15.887 58.912,15.887 103.912,15.887 105.35,15.887 106.912,15.887 108.412,15.887 61.126,15.963 66.229,15.963 82.25,15.963 13.05,16.275 55.777,16.419 64.925,16.443 20.46,16.464 21.794,16.464 23.127,16.464 24.46,16.464 5.335,16.687 11.375,16.744 36.744,16.913 63.655,16.924 84.613,17.172 5.662,17.387 41.662,17.387 43.162,17.387 44.662,17.387 46.162,17.387 47.662,17.387 49.162,17.387 53.662,17.387 55.162,17.387 56.662,17.387 59.662,17.387 86.662,17.387 88.162,17.387 97.162,17.387 98.662,17.387 106.162,17.387 107.662,17.387 109.162,17.387 62.354,17.411 20.46,17.664 21.794,17.664 23.127,17.664 24.46,17.664 8.771,17.727 1.125,17.732 34.233,17.812 3.725,17.886 57.788,17.894 61.115,17.903 101.913,17.887 30.306,18.101 9.548,18.552 12.275,18.672 10.912,18.887 13.912,18.887 16.65,18.879 42.412,18.887 43.912,18.887 45.412,18.887 46.912,18.887 48.412,18.887 49.912,18.887 52.912,18.887 54.412,18.887 55.912,18.887 57.8,18.875 59.8,18.875 96.412,18.887 97.912,18.887 99.412,18.887 100.912,18.887 105.324,18.887 106.912,18.887 108.412,18.887 104.351,18.9 109.729,19.15 40.875,19.199 34.95,19.235 52.205,19.313 56.649,19.339 8.775,19.375 15.169,19.491 102.993,19.625 0.78,19.754 5.335,19.769 100.076,19.8 8.529,20.25 9.318,20.25 31.398,20.313 46.404,20.317 42.786,20.325 10.162,20.387 11.662,20.387 13.162,20.387 98.662,20.387 101.662,20.387 107.662,20.387 109.162,20.387 16.361,20.49 27.575,20.535 2.755,20.685 70.667,20.85 73.213,20.85 76.033,20.835 55.389,20.869 57.95,20.875 60.427,20.875 63.015,20.875 65.534,20.875 68.188,20.875 52.829,20.88 7.168,20.921 7.779,20.925 8.529,20.925 14.292,21.012 40.95,21.018 9.318,21.041 12.19,21.05 78.405,21.35 15.575,21.625 103.604,21.625 101.998,21.7 5.845,21.797 1.912,21.887 3.412,21.887 30.412,21.887 44.004,21.881 48.412,21.887 52.912,21.887 76.912,21.887 99.412,21.887 100.912,21.887 25.837,21.948 28.251,21.959 108.457,22.13 41.525,22.16 77.967,22.21 12.196,22.436 20.506,22.531 14.242,22.718 105.817,22.792 0.78,22.81 21.3,22.85 109.729,23.025 11.479,23.085 50.602,23.071 15.525,23.169 74.484,23.177 26.11,23.254 31.398,23.354 103.107,23.367 2.662,23.387 65.662,23.387 73.162,23.387 100.162,23.387 101.662,23.387 107.662,23.387 8.517,23.417 11.966,23.455 41.225,23.461 104.354,23.708 80.648,23.76 29.542,23.819 74.484,23.828 88.472,23.835 90.988,23.835 5.5,24.175 75.542,24.165 70.775,24.203 73.129,24.203 63.07,24.211 68.139,24.223 60.503,24.244 55.494,24.26 57.937,24.274 65.601,24.265 82.805,24.286 19.394,24.429 88.004,24.415 14.925,24.625 107.854,24.825 1.912,24.887 3.412,24.887 49.912,24.887 81.412,24.887 100.912,24.887 103.912,24.887 109.224,25.035 30.506,25.048 28.15,25.234 77.425,25.25 55.14,25.297 13.625,25.3 47.839,25.343 51.65,25.332 40.75,25.35 44.3,25.35 12.26,25.387 88.775,25.5 89.775,25.5 90.775,25.5 16.13,25.583 17.651,25.59 80.65,25.585 87.013,25.724 92.564,25.734 24.634,25.81 99.85,25.996 103.084,26 105.625,26 11.55,26.025 53.45,26.098 12.347,26.15 63.02,26.205 65.582,26.198 57.911,26.22 60.503,26.213 68.103,26.22 70.644,26.22 73.2,26.22 55.743,26.242 2.662,26.387 14.662,26.387 19.162,26.387 20.662,26.387 23.662,26.387 29.662,26.387 31.162,26.387 49.162,26.387 101.662,26.387 107.662,26.387 5.796,26.498 88.775,26.5 89.775,26.5 90.775,26.5 28.164,26.72 51.649,26.785 0.78,26.804 109.71,26.805 33.425,26.865 75.45,26.852 42.759,26.888 45.284,26.885 13.197,26.95 87.013,27.009 92.556,27 7.171,27.325 7.779,27.325 8.529,27.325 51.649,27.41 18.869,27.441 79.969,27.45 104.646,27.45 2.517,27.497 88.775,27.5 89.775,27.5 90.775,27.5 108.599,27.516 40.329,27.561 42.759,27.622 45.299,27.622 96.624,27.812 9.225,27.825 12.412,27.887 13.912,27.887 19.912,27.887 30.412,27.887 31.912,27.887 43.912,27.887 49.912,27.887 81.412,27.887 103.912,27.887 106.912,27.887 50.668,27.95 47.946,27.974 8.283,28.065 9.824,28.225 87.01,28.26 101.946,28.341 5.4,28.459 10.596,28.452 88.775,28.5 89.775,28.5 83.028,28.54 105.65,28.75 43.975,28.775 108.279,28.8 93.503,28.905 102.699,28.924 75.605,29.083 76.925,29.083 8.713,29.175 5.662,29.387 13.162,29.387 14.662,29.387 16.162,29.387 20.662,29.387 22.162,29.387 23.662,29.387 29.662,29.387 31.162,29.387 32.662,29.387 49.162,29.387 80.662,29.387 82.162,29.387 106.162,29.387 109.162,29.387 9.721,29.425 103.78,29.414 92.545,29.475 97.305,29.502 95.667,29.542 10.662,29.6 17.664,29.675 88.775,29.78 90.762,29.78 41.233,29.935 46.6,29.925 50.748,29.935 104.635,30.02 52.812,30.025 70.662,30.073 73.404,30.1 107.658,30.128 65.57,30.15 68.178,30.15 77.072,30.222 109.718,30.329 0.78,30.387 6.919,30.387 54.076,30.647 63.655,30.645 57.663,30.676 61.175,30.699 1.912,30.887 3.412,30.887 7.912,30.887 13.912,30.887 15.412,30.887 16.912,30.887 21.412,30.887 22.912,30.887 24.412,30.887 27.262,30.887 28.912,30.887 30.412,30.887 31.912,30.887 81.412,30.887 82.912,30.887 106.912,30.887 108.412,30.887 105.625,30.925 103.725,31.325 104.653,31.689 18.869,31.8 87.73,31.896 107.279,32.248 109.224,32.252 105.625,32.275 2.662,32.387 5.662,32.387 7.162,32.387 13.162,32.387 14.662,32.387 16.162,32.387 20.662,32.387 22.162,32.387 23.662,32.387 28.162,32.387 29.662,32.387 31.162,32.387 32.662,32.387 82.162,32.387 83.662,32.387 101.45,32.725 81.625,33.005 86.525,33.025 104.344,33.025 46.6,33.05 90.525,33.05 91.513,33.063 92.5,33.05 57.329,33.125 50.748,33.216 40.365,33.355 43.73,33.383 48.86,33.399 52.823,33.399 106.107,33.42 108.005,33.42 55.353,33.438 96.805,33.73 98.005,33.73 99.205,33.73 100.405,33.73 109.788,33.73 1.912,33.887 3.412,33.887 6.412,33.887 7.912,33.887 9.412,33.887 13.912,33.887 15.412,33.887 16.912,33.887 19.912,33.887 21.412,33.887 22.912,33.887 24.412,33.887 27.223,33.903 28.912,33.887 30.412,33.887 31.912,33.887 33.412,33.887 34.912,33.887 49.912,33.887 17.664,33.975 107.045,33.989 108.955,33.989 75.657,34.081 68.125,34.106 70.662,34.106 104.115,34.105 105.25,34.093 73.204,34.127 58.043,34.375 60.552,34.375 63.079,34.375 65.657,34.406 106.107,34.685 104.646,34.736 41.55,34.85 96.805,34.93 98.005,34.93 99.205,34.93 100.405,34.93 104.149,35.154 105.121,35.154 0.78,35.387 2.662,35.387 5.662,35.387 7.162,35.387 8.662,35.387 10.162,35.387 13.162,35.387 14.662,35.387 16.162,35.387 20.662,35.387 22.162,35.387 23.662,35.387 28.162,35.387 29.662,35.387 31.162,35.387 32.662,35.387 34.162,35.387 35.662,35.387 49.162,35.387 65.662,35.387 73.162,35.387 76.162,35.387 43.975,35.478 50.707,35.655 18.832,35.798 74.475,36.074 52.575,36.1 96.805,36.13 98.005,36.13 99.205,36.13 100.405,36.13 79.134,36.15 104.068,36.525 105.3,36.525 41.478,36.617 74.475,36.725 106.2,36.755 1.912,36.887 3.412,36.887 6.412,36.887 7.912,36.887 9.412,36.887 13.912,36.887 15.412,36.887 16.912,36.887 19.912,36.887 21.412,36.887 22.912,36.887 24.412,36.887 28.912,36.887 30.412,36.887 33.412,36.887 34.912,36.887 43.912,36.887 48.412,36.887 49.912,36.887 52.912,36.887 76.912,36.887 78.2,37.052 92.225,37.075 103.825,37.225 104.695,37.225 96.805,37.33 99.205,37.33 100.405,37.33 109.78,37.38 107.055,37.456 108.955,37.456 105.826,37.524 17.717,37.622 24.479,37.936 27.24,37.931 40.225,37.975 42.681,37.973 48.278,37.975 86.525,38.04 56.729,38.107 59.275,38.1 61.775,38.1 64.352,38.115 66.864,38.115 45.299,38.127 69.429,38.127 108.005,38.238 95.041,38.273 95.845,38.28 50.905,38.347 2.662,38.387 4.162,38.387 7.162,38.387 8.662,38.387 14.662,38.387 16.162,38.387 19.162,38.387 20.662,38.387 22.162,38.387 23.662,38.387 34.162,38.387 35.662,38.387 46.162,38.387 49.162,38.387 55.162,38.387 58.162,38.387 70.162,38.387 74.662,38.387 76.162,38.387 109.162,38.387 85.044,38.7 105.741,38.7 53.656,38.764 76.917,38.764 73.162,38.846 93.9,38.944 109.76,39.33 60.594,39.451 63.274,39.45 55.417,39.494 58.092,39.476 42.759,39.588 45.284,39.585 51.629,39.585 93.057,39.665 65.374,39.716 67.95,39.721 31.243,39.759 18.832,39.777 1.912,39.887 3.412,39.887 4.912,39.887 9.412,39.887 15.412,39.887 16.912,39.887 19.912,39.887 21.412,39.887 22.692,39.9 33.412,39.887 34.912,39.887 40.951,39.9 43.912,39.887 48.412,39.887 49.912,39.887 84.412,39.887 106.277,39.93 25.15,39.975 28.025,39.975 42.759,40.322 45.299,40.322 51.65,40.325 0.78,40.355 108.005,40.403 102.025,40.45 50.662,40.64 86.525,40.75 77.187,40.83 83.625,40.867 84.929,40.855 94.317,40.867 23.803,40.927 103.073,40.987 29.75,41.325 2.662,41.387 4.162,41.387 5.662,41.387 7.162,41.387 19.162,41.387 34.162,41.387 35.662,41.387 49.162,41.387 107.662,41.387 109.76,41.53 95.005,41.571 96.728,41.596 17.717,41.605 14.684,41.686 105.826,41.717 75.605,41.781 28.1,41.807 12.33,41.907 21.125,41.9 22.25,41.9 101.876,42.05 41.225,42.2 44.004,42.193 81.558,42.249 94.459,42.258 96.25,42.255 92.925,42.275 97.341,42.278 55.389,42.404 57.985,42.45 60.526,42.45 63.086,42.505 108.736,42.517 19.748,42.521 16.963,42.57 70.5,42.615 103.05,42.75 46.525,42.863 1.912,42.887 3.412,42.887 4.912,42.887 6.412,42.887 7.912,42.887 33.412,42.887 34.912,42.887 49.912,42.887 54.412,42.887 58.912,42.887 61.912,42.887 103.912,42.887 106.912,42.887 50.748,42.931 52.95,42.961 28.1,43.3 101.875,43.425 105.236,43.42 109.739,43.48 23.792,43.496 68.959,43.525 30.17,43.906 32.653,43.895 37.1,44.02 38.128,44.067 12.258,44.1 13.61,44.096 61.3,44.347 65.534,44.347 57.363,44.371 2.662,44.387 4.162,44.387 5.662,44.387 7.162,44.387 34.162,44.387 35.662,44.387 58.162,44.387 59.662,44.387 62.662,44.387 64.162,44.387 106.162,44.387 107.662,44.387 109.162,44.387 19.242,44.646 20.442,44.646 21.642,44.646 53.95,44.7 13.61,44.746 101.875,44.8 104.986,44.8 28.1,44.927 78.252,45.563 84.725,45.563 81.375,45.592 87.75,45.575 86.525,45.6 73.162,45.634 0.78,45.647 109.739,45.68 104.993,45.725 19.242,45.846 20.442,45.846 21.642,45.846 1.912,45.887 3.412,45.887 4.912,45.887 6.412,45.887 30.139,45.874 33.412,45.887 34.912,45.887 36.412,45.887 39.412,45.887 49.912,45.887 52.95,45.889 79.912,45.887 88.912,45.887 90.412,45.887 100.912,45.887 106.912,45.887 108.412,45.887 12.58,45.946 10.6,45.988 55.65,45.975 59.248,45.975 63.175,45.975 65.57,45.975 68.075,46 70.719,46 41.45,46.026 44.004,46.026 46.1,46.2 48.86,46.2 50.707,46.201 29.675,46.45 19.242,47.046 20.442,47.046 21.642,47.046 58.2,47.075 39.328,47.15 24.867,47.246 27,47.25 2.662,47.387 5.662,47.387 10.162,47.387 34.162,47.387 35.662,47.387 49.162,47.387 77.662,47.387 79.162,47.387 80.662,47.387 82.162,47.387 88.162,47.387 89.662,47.387 91.162,47.387 100.162,47.387 106.162,47.387 107.662,47.387 14.125,47.425 41.525,47.549 109.718,47.63 29.675,47.75 46.439,47.769 47.839,47.769 4.412,47.871 75.779,47.949 52.677,48.025 55.65,48.025 84.725,48.025 14.125,48.091 80.998,48.175 43.906,48.234 24.087,48.264 30.225,48.329 1.912,48.887 3.412,48.887 4.912,48.887 6.412,48.887 33.412,48.887 34.912,48.887 39.412,48.887 40.912,48.887 49.912,48.887 76.912,48.887 78.412,48.887 79.912,48.887 81.412,48.887 88.912,48.887 90.412,48.887 91.912,48.887 93.412,48.887 94.912,48.887 96.412,48.887 97.912,48.887 99.412,48.887 100.912,48.887 105.412,48.887 106.912,48.887 108.412,48.887 9.725,48.898 23.025,48.955 24.867,48.975 17.055,49.05 50.707,49.164 36.174,49.2 74.504,49.225 52.6,49.308 19.217,49.455 55.65,49.475 65.613,49.475 68.088,49.475 70.675,49.475 82.75,49.475 58.2,49.5 60.488,49.5 63.138,49.5 73.231,49.5 41.157,49.598 47.819,49.6 21.225,49.775 30.225,49.949 44.004,49.997 38.625,50.048 74.5,50.15 37.135,50.287 28.001,50.31 17.425,50.332 18.9,50.325 20.7,50.325 32.824,50.343 34.975,50.35 109.713,50.35 4.162,50.387 47.662,50.387 49.162,50.387 59.662,50.387 61.162,50.387 62.662,50.387 64.162,50.387 65.662,50.387 67.162,50.387 68.662,50.387 70.162,50.387 71.662,50.387 73.162,50.387 76.162,50.387 77.662,50.387 79.162,50.387 80.662,50.387 82.162,50.387 89.662,50.387 91.162,50.387 92.662,50.387 94.162,50.387 95.662,50.387 97.162,50.387 98.662,50.387 100.162,50.387 101.662,50.387 104.662,50.387 106.162,50.387 107.662,50.387 0.775,50.7 3.17,50.7 5.662,50.7 54.164,50.725 57.125,50.728 84.712,50.875 86.525,50.875 87.75,50.875 9.725,51.263 78.025,51.29 42.734,51.461 45.274,51.461 48.379,51.85 1.912,51.887 3.412,51.887 4.912,51.887 76.912,51.887 79.912,51.887 81.412,51.887 88.912,51.887 90.412,51.887 91.912,51.887 93.412,51.887 94.912,51.887 96.412,51.887 97.912,51.887 99.412,51.887 100.912,51.887 105.412,51.887 106.912,51.887 108.412,51.887 65.6,51.95 68.075,51.95 70.662,51.95 50.625,51.975 52.65,51.975 58.012,51.975 60.475,51.975 63.125,51.975 73.231,51.975 30.17,52.001 37.047,52.001 27.984,52.025 32.85,52.025 34.975,52.025 39.175,52.025 55.417,52.025 18.209,52.048 26.142,52.048 21.932,52.104 24.319,52.152 20.4,52.45 82.369,52.504 109.713,52.7 84.481,52.894 2.075,53.125 18.231,53.274 89.662,53.387 91.162,53.387 92.662,53.387 94.162,53.387 95.662,53.387 97.162,53.387 98.662,53.387 100.162,53.387 101.662,53.387 104.662,53.387 106.162,53.387 107.662,53.387 109.162,53.387 23.499,53.575 25.138,53.611 22.014,54.114 5.55,54.422 9.75,54.41 109.692,54.65 83.162,54.698 75.525,54.72 76.975,54.72 78.741,54.72 80.677,54.72 88.604,54.781 84.412,54.887 90.412,54.887 91.912,54.887 93.412,54.887 94.912,54.887 100.912,54.887 106.912,54.887 108.412,54.887 30.098,54.931 32.823,54.925 46.82,54.925 31.675,54.947 34.95,54.954 49.75,54.954 37.025,54.975 40.711,54.975 96.696,55.049 101.664,55.049 103.973,55.049 66.05,55.152 68.582,55.152 71.082,55.152 73.7,55.152 42.734,55.184 45.275,55.175 51.629,55.179 53.2,55.175 55.9,55.182 58.45,55.175 60.95,55.175 63.45,55.175 23.317,55.289 0.775,55.312 20.348,55.488 25.278,55.551 12.5,55.6 27.542,55.902 22.431,55.988 18.415,56.153 33.803,56.277 36.134,56.274 39.282,56.299 49.162,56.387 50.662,56.387 52.162,56.387 53.662,56.387 55.162,56.387 56.662,56.387 58.162,56.387 59.662,56.387 61.162,56.387 62.662,56.387 64.162,56.387 65.662,56.387 67.162,56.387 68.662,56.387 70.162,56.387 71.662,56.387 73.162,56.387 74.662,56.387 76.162,56.387 77.662,56.387 79.162,56.387 80.662,56.387 82.162,56.387 83.662,56.387 91.162,56.387 92.662,56.387 94.162,56.387 95.662,56.387 107.662,56.387 10.475,56.425 14.646,56.425 41.879,56.417 100.454,56.435 46.169,56.536 87.129,56.595 102.811,56.698 103.973,56.698 6.271,56.738 96.686,56.777 109.692,56.85 24.479,56.9 20.478,57 31.595,57.025 91.006,57.368 21.412,57.887 33.412,57.887 34.912,57.887 36.412,57.887 39.412,57.887 51.412,57.887 52.912,57.887 54.412,57.887 55.912,57.887 57.412,57.887 58.912,57.887 60.412,57.887 61.912,57.887 63.412,57.887 64.912,57.887 66.412,57.887 67.912,57.887 69.412,57.887 70.912,57.887 72.412,57.887 73.912,57.887 75.412,57.887 76.912,57.887 78.412,57.887 79.912,57.887 81.412,57.887 82.912,57.887 87.412,57.887 106.912,57.887 108.412,57.887 29.595,58.026 97.976,58.25 99.417,58.277 102.813,58.349 104.756,58.349 27.084,58.4 109.692,58.492 9.684,58.5 24.7,58.5 30.917,58.513 7.684,58.525 15.505,58.525 41.077,58.55 18.209,58.871 30.912,59.141 46.825,59.268 49.51,59.268 4.521,59.305 29.662,59.387 34.2,59.387 40.162,59.387 47.662,59.387 52.162,59.387 53.662,59.387 55.162,59.387 56.662,59.387 58.162,59.387 59.662,59.387 61.162,59.387 62.662,59.387 64.162,59.387 65.662,59.387 67.162,59.387 68.662,59.387 70.162,59.387 71.662,59.387 73.162,59.387 74.662,59.387 76.162,59.387 77.662,59.387 79.162,59.387 80.662,59.387 82.162,59.387 83.662,59.387 86.662,59.387 91.162,59.387 92.662,59.387 94.162,59.387 95.662,59.387 107.662,59.387 109.162,59.387 100.445,59.466 0.775,59.693 109.671,60.1 14.808,60.4 101.603,60.47 29.59,60.542 10.59,60.6 27.072,60.615 33.05,60.615 20.525,60.65 24.036,60.65 9.412,60.887 15.412,60.887 16.912,60.887 18.412,60.887 21.412,60.887 22.912,60.887 39.412,60.887 40.912,60.887 42.25,60.9 46.912,60.887 48.412,60.887 49.912,60.887 102.412,60.887 103.912,60.887 105.856,60.899 106.912,60.887 99.35,61 101.039,61.025 61.375,61.095 72.412,61.098 76.377,61.11 84,61.11 91.978,61.098 95.865,61.098 57.15,61.113 53.633,61.162 68.582,61.15 80.475,61.15 65.125,61.196 87.826,61.21 108.625,61.21 45.05,61.225 12.8,61.425 30.917,61.468 30.912,62.071 0.78,62.625 10.936,62.629 13.695,62.625 16.482,62.629 19.241,62.625 22.028,62.629 24.787,62.625 27.175,62.625 29.595,62.625 32.251,62.625 35.05,62.625 40.625,62.625 43.792,62.625 47.638,62.625 51.485,62.625 55.332,62.625 59.179,62.625 63.026,62.625 66.872,62.625 70.719,62.625 74.566,62.625 78.413,62.625 82.259,62.625 86.106,62.625 89.953,62.625 93.8,62.625 97.647,62.625 101.493,62.625 105.34,62.625 3.719,62.65 7.501,62.65 37.927,62.65 109.222,62.727
  other v2: 30.415,11.84 30.415,16.1 15.601,16.385 16.146,16.386 15.826,18.576 85.464,24.44 86.942,24.44 85.902,26.425 86.635,29.502
  other v3: 16.2,10.76 12.947,14.144 14.215,14.907 15.531,15.336 8.775,18.552 24.655,22.884 27.77,22.876 11.579,23.833 25.297,24.901 11.579,25.449 10.6,27.825 18.109,43.578 25.61,45.096 23.574,46.596
LED_PWR_CTRL: U2.A17 U10.8 | length 39.3
  Top Layer w0.125: U2.A17@22.46,19.064 22.46,19.287 22.692,19.519 22.692,22.288 22.88,22.475 23.63,22.475 24.275,23.12 v1(24.275,23.5)
  Top Layer w0.15: U10.8@22.892,47.596 23.49,47.596 23.604,47.71 23.604,49.471 v1(23.6,49.475)
  Bottom Layer w0.125: v1(23.6,49.475) 23.696,49.475 23.861,49.64 26.523,49.64 27.5,48.663 27.5,47.075 25.8,45.375 25.8,24.55 24.75,23.5 v1(24.275,23.5)
NetC6_2: C6.2 L2.2 L3.1 | length 0.9
  Top Layer w0.27: L2.2@103.058,35.73 C6.2@103.058,36.25
  Top Layer w0.3: L2.2@103.13,35.73 L3.1@103.5,35.73
NetC9_2: C9.2 L3.2 L4.1 | length 0.9
  Top Layer w0.3: L3.2@104.149,35.73 C9.2@104.635,35.73 L4.1@105.065,35.73
NetC21_1: C21.1 R39.2 SB9.2 SB10.2 U9.8 | length 9.1
  Top Layer w0.125: C21.1@87.422,23.842 87.422,23.553 87.801,23.174 91.174,23.174 91.537,23.537 R39.2@91.537,23.835
  Top Layer w0.25: 84.997,23.794 85.045,23.842 SB10.2@86.347,23.842 C21.1@87.422,23.842 87.422,24.995 87.322,25.095 U9.8@87.005,25.095
NetC27_2: C27.2 C57.2 FB3.1 L8.1 U10.1 | length 15.1
  Top Layer w0.15: U10.1@22.892,44.096 22.892,41.657 23.068,41.481 24.924,41.481
  Top Layer w0.75: C27.2@24.924,42.186 24.924,41.481 24.924,41.189 25.363,40.75 28.15,40.75 28.9,41.5 28.9,45.874 FB3.1@28.9,46.55
NetC32_2: C32.2 C33.1 U2.A27 U2.G31 | length 8.9
  Top Layer w0.15: C32.2@24.953,20.385 C32.2@25.032,20.306
  Top Layer w0.2: U2.A27@24.46,19.064 24.46,19.64 24.801,19.98 C32.2@24.801,20.381 ; C32.2@24.803,20.535 24.953,20.385 C32.2@24.953,20.34 ; C32.2@25.032,20.306 v1(25.512,20.306) ; U2.G31@25.46,17.664 27.185,17.664 27.409,17.889 27.409,18.056 27.444,18.091 C33.1@27.459,18.091 27.494,18.056 27.618,18.056 v1@27.884,17.79
  Bottom Layer w0.2: v1(25.512,20.306) 25.512,19.719 27.441,17.79 v1(27.885,17.79)
NetC39_2: C39.2 U2.A15 | length 2.8
  Top Layer w0.225: U2.A15@22.06,19.064 22.06,19.42 22.286,19.646 22.286,21.619 C39.2@22.151,21.754
NetC42_1: C42.1 R40.1 U2.A5 U2.E1 | length 7.9
  Top Layer w0.15: C42.1@17,21.184 C42.1@17.231,20.952 ; C42.1@17.226,20.947 17.866,20.306 19.231,20.306 v1(19.275,20.35) 19.347,20.35 20.06,19.637 U2.A5@20.06,19.064
  Top Layer w0.2: v1@18.577,18.152 18.966,18.152 19.054,18.064 U2.E1@19.06,18.064
  Top Layer w0.25: R40.1@16.394,21.184 C42.1@17,21.184
  Bottom Layer w0.2: v1(18.575,18.15) 18.575,19.65 v1(19.275,20.35)
NetC43_1: C43.1 U2.B6 | length 3.7
  Top Layer w0.15: C43.1@18.527,20.825 19.472,20.825 19.75,20.547 19.75,20.475 20.235,19.99 20.391,19.834 20.391,18.938 ; U2.B6@20.26,18.664 20.391,18.934
  Top Layer w0.187: C43.1@18.4,20.952 C43.1@18.552,20.8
